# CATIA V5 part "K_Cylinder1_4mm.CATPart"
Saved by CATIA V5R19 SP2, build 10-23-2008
Part number: Liant2
Bounding box of the stored display mesh (mm): x 0 to 8, y -2 to 2, z -2 to 2
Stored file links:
  G:\Khaled_CFAO_2011\ST2M\ST2M_GR1\bgaltie\bgaltie\Khaled\CAD_thinkMOTION\K_Cylinder1_4mm.CATPart
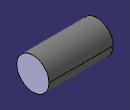
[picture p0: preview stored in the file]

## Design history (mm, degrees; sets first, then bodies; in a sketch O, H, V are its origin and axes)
AxisSystem1: origin (0, 0, 0), X (1, 0, 0), Y (0, 1, 0), Z (0, 0, 1)
Body1 (main body)
  Sketch1 on YZ plane of AxisSystem1, origin (0, 0, 0), H (0, 1, 0), V (0, 0, 1)
    circle A1 centre (0, 0) radius 2
    point P1 (0, 0)
    radius A1 = 2
    coincidence: P1 O
  Pad1: profile Sketch1, direction (1, 0, 0), length 8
